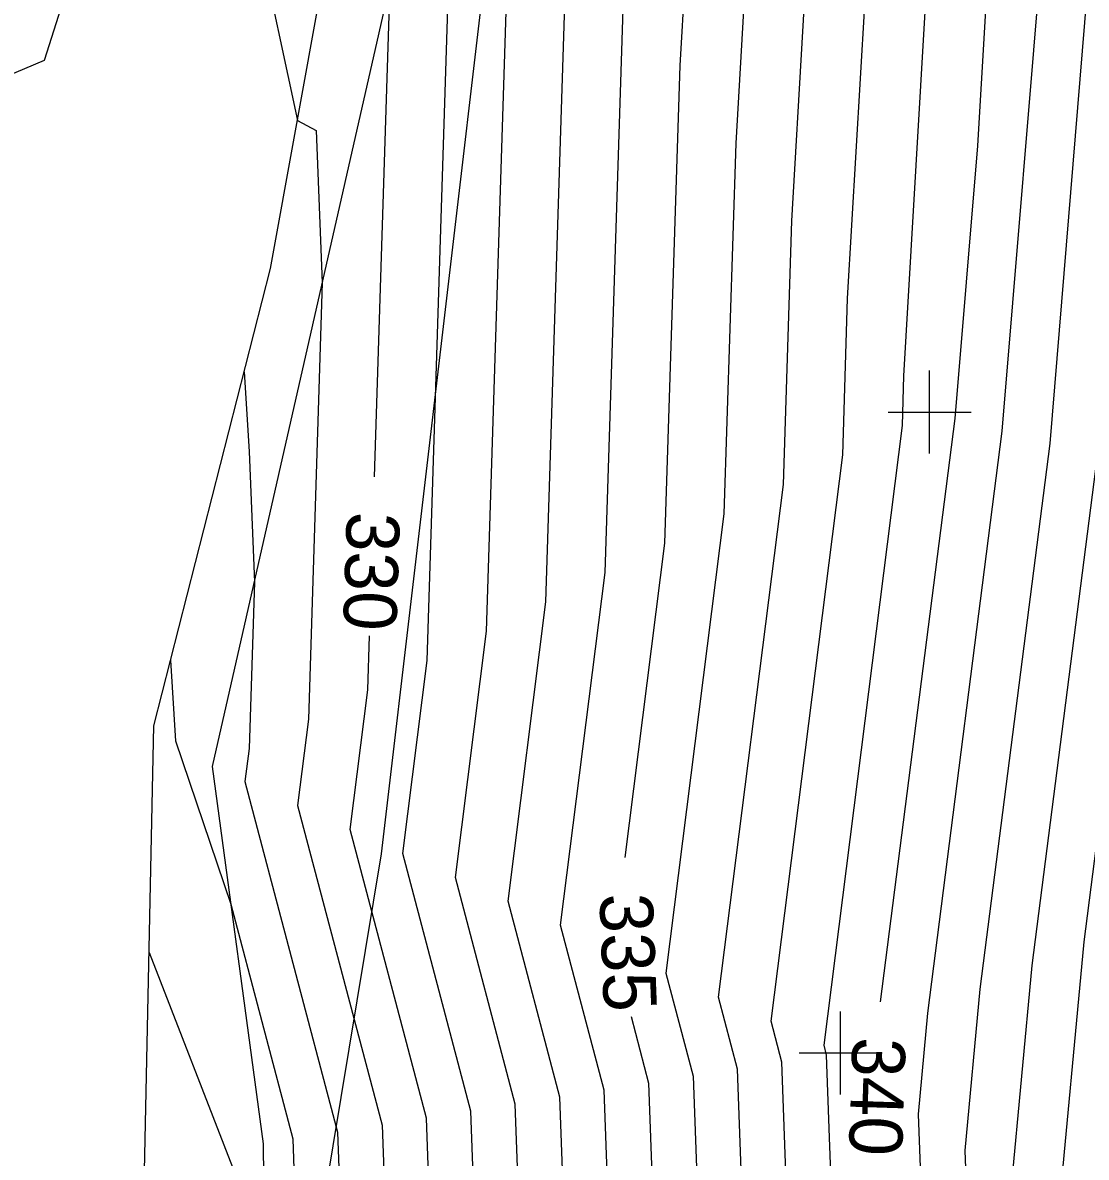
# Model space of a CAD drawing. Extents: x 487096 to 489566, y 221939 to 224454.
# Drawn here: x 488276.8 to 488340.9, y 223351.6 to 223420 of the extents above; entities that cross this region are included whole.
import ezdxf

# ---------------------------------------------------------------- set-up
doc = ezdxf.new("R2010")
doc.units = 0
for name, color, linetype in [('SV_BKLN_BKLN', 7, 'Continuous'), ('SV_SURF_INDEX_CONTOUR', 7, 'Continuous'), ('SV_SURF_INTER_CONTOUR', 7, 'Continuous'), ('SV_SURF_SPOT', 7, 'Continuous'), ('SV_WATR_INWETF', 7, 'Continuous'), ('SV_WATR_STREAM', 7, 'Continuous')]:
    doc.layers.add(name, color=color, linetype=linetype)

msp = doc.modelspace()

# ---------------------------------------------------------------- linework, layer by layer
at = {"layer": 'SV_BKLN_BKLN'}
msp.add_lwpolyline([(488284.008, 223344.963), (488284.693, 223377.57), (488291.716, 223405.149), (488297.876, 223439.045)], dxfattribs=at)
at = {"layer": 'SV_SURF_INDEX_CONTOUR'}
for points in [[(488317.472, 223455.742), (488317.874, 223442.758), (488317.288, 223432.855), (488316.386, 223417.393), (488315.474, 223388.599), (488313.076, 223369.633)], [(488336.356, 223446.906), (488335.234, 223427.915), (488334.337, 223412.549), (488332.976, 223396.1), (488328.476, 223360.926)], [(488297.991, 223392.6), (488298.933, 223422.332), (488298.77, 223426.452), (488295.869, 223428.002), (488294.814, 223432.933), (488293.666, 223437.103), (488292.29, 223433.747), (488286.2, 223421.925)], [(488307.444, 223297.676), (488307.253, 223298.669), (488305.118, 223313.109), (488301.592, 223340.939), (488301.118, 223353.915), (488296.52, 223371.332), (488297.584, 223379.749), (488297.688, 223383.004)], [(488313.45, 223360.04), (488314.509, 223356.028), (488315.628, 223325.353), (488316.6, 223317.677), (488317.189, 223313.694), (488324.556, 223275.309), (488324.53, 223274.985), (488324.55, 223274.705)]]:
    msp.add_lwpolyline(points, dxfattribs=at)
at = {"layer": 'SV_SURF_INTER_CONTOUR'}
for points in [[(488342.405, 223523.227), (488342.938, 223493.507), (488343.029, 223493.284), (488343.959, 223452.763), (488343.962, 223452.75), (488343.964, 223452.738), (488343.966, 223452.726), (488343.967, 223452.715), (488343.967, 223452.704), (488343.967, 223452.694), (488343.967, 223452.684), (488343.966, 223452.681), (488343.975, 223452.397), (488343.931, 223451.656), (488341.496, 223428.002), (488341.069, 223423.434), (488338.683, 223394.606), (488334.471, 223361.687), (488333.572, 223351.971), (488334.716, 223321.625)], [(488346.357, 223521.53), (488346.85, 223494.014), (488346.934, 223493.808), (488347.806, 223455.852), (488346.826, 223451.209), (488344.476, 223428.386), (488343.764, 223420.78), (488341.536, 223393.859), (488337.604, 223363.118), (488336.368, 223349.775), (488337.413, 223322.059), (488344.813, 223296.595), (488348.741, 223278.32), (488353.119, 223244.108), (488359.768, 223236.874), (488370.825, 223218.92)], [(488350.309, 223519.833), (488350.762, 223494.521), (488350.84, 223494.332), (488351.641, 223459.416), (488349.63, 223449.885), (488347.456, 223428.77), (488346.46, 223418.125), (488344.39, 223393.112), (488340.736, 223364.549), (488339.164, 223347.579), (488340.11, 223322.492), (488348.724, 223292.851), (488351.765, 223278.701), (488355.155, 223252.212), (488363.19, 223243.47), (488376.551, 223221.776), (488378.02, 223207.425)], [(488320.594, 223209.107), (488317.309, 223255.078), (488319.07, 223277.176), (488313.215, 223307.684), (488312.007, 223315.85), (488310.013, 223331.587), (488309.153, 223355.183), (488306.035, 223366.994), (488308.318, 223385.059), (488309.639, 223426.754), (488310.11, 223434.831), (488310.416, 223440.004), (488309.761, 223461.164), (488307.732, 223462.227), (488308.954, 223474.096), (488303.636, 223466.041), (488302.905, 223468.698), (488298.726, 223458.507), (488295.426, 223452.101), (488285.665, 223455.591), (488279.114, 223460.734), (488240.248, 223486.418)], [(488316.219, 223209.854), (488313.699, 223245.125), (488316.327, 223278.11), (488311.228, 223304.679), (488309.711, 223314.936), (488307.206, 223334.704), (488306.474, 223354.761), (488302.863, 223368.44), (488304.74, 223383.289), (488306.265, 223431.434), (488306.521, 223435.818), (488306.687, 223438.627), (488306.332, 223450.114), (488303.265, 223451.72), (488303.933, 223458.21), (488301.025, 223453.805), (488299.825, 223458.167), (488296.581, 223450.253), (488292.115, 223441.585), (488285.759, 223443.858), (488281.493, 223447.207), (488226.844, 223483.321)], [(488311.844, 223210.602), (488310.088, 223235.171), (488313.584, 223279.043), (488309.241, 223301.674), (488307.414, 223314.023), (488304.399, 223337.821), (488303.796, 223354.338), (488299.692, 223369.886), (488301.162, 223381.519), (488302.892, 223436.114), (488302.932, 223436.806), (488302.958, 223437.25), (488302.902, 223439.063), (488298.798, 223441.213), (488298.912, 223442.323), (488298.415, 223441.57), (488296.746, 223447.635), (488294.435, 223442), (488288.804, 223431.069), (488285.853, 223432.124), (488283.873, 223433.679), (488213.44, 223480.224)], [(488320.877, 223431.867), (488319.76, 223412.713), (488319.052, 223390.369), (488315.549, 223362.656), (488317.187, 223356.451), (488318.435, 223322.236)], [(488321.176, 223320.936), (488319.865, 223356.873), (488318.72, 223361.21), (488322.63, 223392.139), (488323.134, 223408.033), (488324.466, 223430.879)], [(488323.289, 223336.842), (488322.543, 223357.296), (488321.891, 223359.764), (488326.208, 223393.909), (488326.507, 223403.353), (488328.055, 223429.891)], [(488331.645, 223428.903), (488329.881, 223398.673), (488329.786, 223395.679), (488325.063, 223358.318), (488325.221, 223357.719), (488325.402, 223352.749), (488326.625, 223320.325)], [(488288.189, 223421.697), (488290.145, 223425.493), (488290.587, 223426.571), (488290.955, 223425.232), (488293.34, 223414.087), (488294.475, 223413.481), (488294.84, 223404.289), (488294.006, 223377.978), (488293.349, 223372.779), (488298.44, 223353.493), (488298.784, 223344.056), (488302.821, 223312.195), (488305.266, 223295.664), (488308.097, 223280.91), (488302.867, 223215.264)], [(488332.019, 223321.192), (488330.775, 223354.167), (488331.339, 223360.257), (488335.829, 223395.353), (488338.373, 223426.089)], [(488312.82, 223328.47), (488311.831, 223355.606), (488309.206, 223365.548), (488311.896, 223386.829), (488313.013, 223422.074)], [(488290.132, 223398.93), (488290.433, 223394.127), (488290.746, 223386.246), (488290.428, 223376.208), (488290.178, 223374.225), (488295.762, 223353.07), (488295.977, 223347.173), (488300.525, 223311.282), (488303.279, 223292.659), (488305.354, 223281.844), (488300.988, 223227.03)], [(488299.835, 223247.925), (488302.611, 223282.777), (488301.292, 223289.654), (488298.228, 223310.368), (488293.17, 223350.29), (488293.084, 223352.648), (488289.346, 223366.809), (488286.011, 223376.653), (488285.704, 223381.543)], [(488284.406, 223363.91), (488289.566, 223350.606), (488291.367, 223345.479), (488295.932, 223309.455), (488299.305, 223286.649), (488299.868, 223283.711), (488298.682, 223268.82)]]:
    msp.add_lwpolyline(points, dxfattribs=at)
at = {"layer": 'SV_SURF_SPOT'}
for p, q in [((488331.447, 223394), (488331.447, 223399.002)), ((488328.946, 223396.501), (488333.948, 223396.501)), ((488331.447, 223396.501), (488331.447, 223396.501)), ((488326.081, 223355.353), (488326.081, 223360.355)), ((488323.58, 223357.854), (488328.582, 223357.854)), ((488326.081, 223357.854), (488326.081, 223357.854))]:
    msp.add_line(p, q, dxfattribs=at)
at = {"layer": 'SV_WATR_INWETF'}
for points in [[(488392.951, 223538.467), (488377.591, 223540.374), (488348.653, 223536.588), (488322.282, 223526.421), (488300.731, 223488.93), (488278.082, 223417.696)], [(488252.554, 223050.251), (488264.25, 223090.229), (488281.906, 223135.609), (488282.575, 223190.441), (488295.504, 223227.967), (488308.746, 223255.149), (488305.197, 223268.339), (488289.173, 223314.006), (488298.401, 223369.864), (488304.627, 223422.704), (488301.311, 223432.187)], [(488278.082, 223417.696), (488212.841, 223390.055), (488178.234, 223322.697)]]:
    msp.add_lwpolyline(points, dxfattribs=at)
at = {"layer": 'SV_WATR_STREAM'}
msp.add_lwpolyline([(488291.736, 223307.785), (488291.3, 223352.366), (488288.221, 223375.117), (488302.259, 223436.992)], dxfattribs=at)

# ---------------------------------------------------------------- texts
at = {"layer": 'SV_SURF_INDEX_CONTOUR'}
for s, rotation, p in [('330', 268.18575, (488296.324, 223390.503)), ('335', 272.20228, (488311.548, 223367.424)), ('340', 268.16916, (488326.807, 223358.83))]:
    msp.add_text(s, height=3.2, rotation=rotation, dxfattribs=at).set_placement(p)

doc.saveas('drawing.dxf')
